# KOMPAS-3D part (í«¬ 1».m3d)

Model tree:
1. Эскиз:1
2. Операция выдавливания:1
     Расстояние 1 = 2
3. Эскиз:2
4. Операция выдавливания:2
     Расстояние 1 = 5
5. Эскиз:3
6. Операция выдавливания:3
     Расстояние 1 = 2
7. Эскиз:4
8. Операция выдавливания:4
     Расстояние 1 = 60
9. Эскиз:5
10. Операция выдавливания:5
     Расстояние 1 = 2
11. Эскиз:6
12. Операция выдавливания:6
     Расстояние 1 = 4.5
13. Эскиз:7
14. Операция выдавливания:7
     Расстояние 1 = 2
15. Скругление:1
     Радиус = 1
16. Скругление:2
     Радиус = 1
17. Эскиз:8
18. Вырезать элемент выдавливания:1
     Расстояние 1 = 10; Угол 1 = 35
19. Эскиз:9
20. Вырезать элемент выдавливания:2
     Расстояние 1 = 10; Угол 1 = 35
21. Эскиз:10
22. Вырезать элемент выдавливания:3
     Расстояние 2 = 22; Расстояние 1 = 22; Угол 1 = 35
23. Эскиз:11
24. Вырезать элемент выдавливания:4
     Расстояние 2 = 2; Расстояние 1 = 2
25. Эскиз:12
26. Вырезать элемент выдавливания:5
     Расстояние 2 = 2; Расстояние 1 = 2; Угол 1 = 35
27. Эскиз:13
28. Вырезать элемент выдавливания:6
     Расстояние 2 = 2; Расстояние 1 = 122
29. Эскиз:15
30. Операция выдавливания:9
     Расстояние 1 = 10; Расстояние 2 = 0.5
